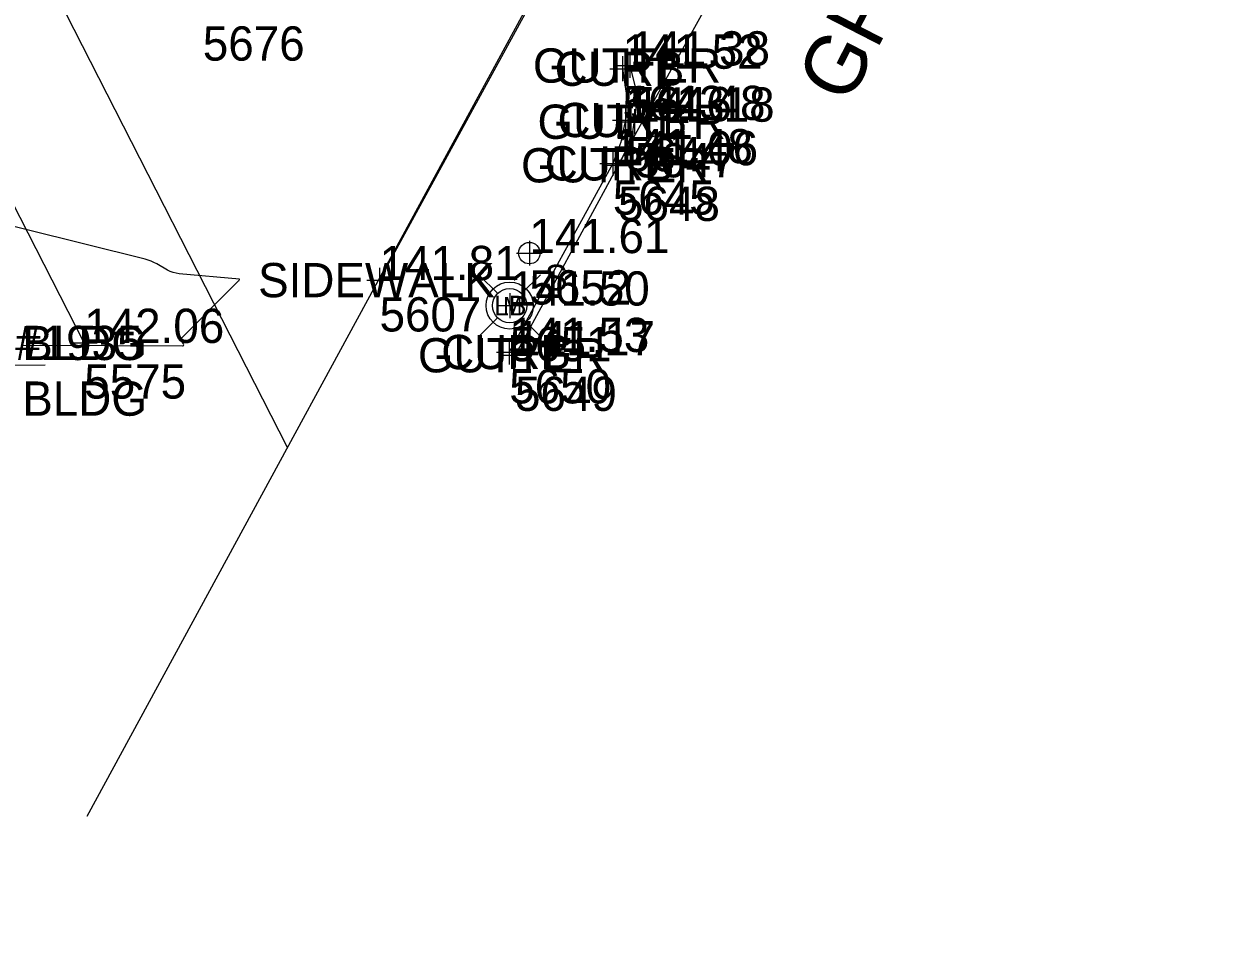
# Model space of a CAD drawing. Extents: x 13482495 to 13483389, y 311646 to 312209.
# Drawn here: x 13483186.7 to 13483297.5, y 311897.5 to 311982.2 of the extents above; entities that cross this region are included whole.
import ezdxf

# ---------------------------------------------------------------- set-up
doc = ezdxf.new("R2010")
doc.units = 0
for name, color, linetype in [('Level 14', 7, 'Continuous'), ('V-ANNO-TEXT', 7, 'Continuous'), ('V-BLDG-OTLN', 7, 'Continuous'), ('V-PROP-LINE', 7, 'Continuous'), ('V-PROP-RWAY', 7, 'Continuous'), ('V-PVMT-BACK', 7, 'Continuous'), ('V-PVMT-ROAD', 7, 'Continuous'), ('V-PVMT-SPOT', 7, 'Continuous'), ('V-SITE-FEAT', 7, 'Continuous'), ('V-SITE-SPOT', 7, 'Continuous'), ('V-SITE-WALK', 7, 'Continuous'), ('V-SURV-PNTS', 7, 'Continuous'), ('V-TOPO-LINE-IDEN', 7, 'Continuous'), ('V-TOPO-MINR', 7, 'Continuous'), ('V-UTIL-OVHD', 7, 'Continuous'), ('V-UTIL-SPOT', 7, 'Continuous')]:
    doc.layers.add(name, color=color, linetype=linetype)

msp = doc.modelspace()

# ---------------------------------------------------------------- linework, layer by layer
at = {"layer": 'Level 14'}
msp.add_circle((13483232.15, 311955.82), 2.2, dxfattribs=at)
at = {"layer": 'V-BLDG-OTLN'}
msp.add_lwpolyline([(13483192.39, 311952.33), (13483171.44, 311993.3), (13483148.19, 311981.61), (13483141.82, 311994.09), (13483137, 311991.7), (13483125.72, 311985.93), (13483092.64, 311968.99), (13483092, 311968.67), (13483074.09, 311959.49), (13483064.66, 311954.6), (13483063.9, 311954.26), (13483051.45, 311947.77), (13483050.51, 311947.31), (13483037.41, 311940.79), (13483029.61, 311936.57), (13483002.49, 311922.78), (13482992.73, 311917.83), (13482979.02, 311910.86), (13482976.31, 311909.36), (13482986.43, 311889.53)], dxfattribs=at)
at = {"layer": 'V-PROP-LINE'}
msp.add_line((13483211.39, 311942.55), (13483176.4, 312011.1), dxfattribs=at)
at = {"layer": 'V-PROP-RWAY'}
msp.add_line((13483192.66, 311908.1), (13483276.39, 312062.11), dxfattribs=at)
at = {"layer": 'V-PVMT-BACK'}
msp.add_lwpolyline([(13483242.7, 311977.95), (13483243.05, 311975.66), (13483243, 311973.36), (13483242.55, 311971.1), (13483241.79, 311969.11), (13483232.11, 311951.48)], dxfattribs=at)
at = {"layer": 'V-PVMT-ROAD'}
for points in [[(13483264.81, 312066.09), (13483266.5, 312067.78), (13483268.45, 312069.17), (13483270.59, 312070.21), (13483272.89, 312070.89), (13483275.26, 312071.17), (13483277.65, 312071.05), (13483279.98, 312070.53), (13483279.99, 312070.53), (13483281.99, 312069.17), (13483283.78, 312067.62), (13483285.28, 312065.79), (13483286.46, 312063.73), (13483287.22, 312061.7), (13483287.93, 312059.34), (13483288.26, 312057.11), (13483288.19, 312054.85), (13483287.73, 312052.64), (13483287.38, 312051.65), (13483273.55, 312025.96), (13483262.05, 312005.41), (13483253.54, 311989.25), (13483242.28, 311968.93), (13483232.65, 311951.18)], [(13483243.39, 311978.25), (13483243.87, 311976.22), (13483243.95, 311974.13), (13483243.63, 311972.07), (13483242.92, 311970.11), (13483242.28, 311968.93)]]:
    msp.add_lwpolyline(points, dxfattribs=at)
at = {"layer": 'V-PVMT-SPOT'}
for p, q in [((13483242.7, 311979.11), (13483242.7, 311976.79)), ((13483243.39, 311979.41), (13483243.39, 311977.09)), ((13483242.19, 311978.25), (13483244.59, 311978.25)), ((13483241.5, 311977.95), (13483243.9, 311977.95)), ((13483242.97, 311974.32), (13483242.97, 311972)), ((13483243.82, 311974.16), (13483243.82, 311971.84)), ((13483241.77, 311973.16), (13483244.17, 311973.16)), ((13483242.62, 311973), (13483245.02, 311973)), ((13483241.79, 311970.27), (13483241.79, 311967.95)), ((13483240.59, 311969.11), (13483242.99, 311969.11)), ((13483242.28, 311970.09), (13483242.28, 311967.77)), ((13483242.28, 311970.09), (13483242.28, 311967.77)), ((13483241.08, 311968.93), (13483243.48, 311968.93)), ((13483241.08, 311968.93), (13483243.48, 311968.93)), ((13483219.99, 311959.36), (13483219.99, 311957.04)), ((13483218.79, 311958.2), (13483221.19, 311958.2)), ((13483232.11, 311952.64), (13483232.11, 311950.32)), ((13483230.91, 311951.48), (13483233.31, 311951.48)), ((13483232.65, 311952.34), (13483232.65, 311950.02)), ((13483231.45, 311951.18), (13483233.85, 311951.18))]:
    msp.add_line(p, q, dxfattribs=at)
at = {"layer": 'V-SITE-FEAT'}
msp.add_circle((13483233.99, 311960.72), 1, dxfattribs=at)
at = {"layer": 'V-SITE-SPOT'}
for p, q in [((13483233.99, 311961.88), (13483233.99, 311959.56)), ((13483232.79, 311960.72), (13483235.19, 311960.72)), ((13483192.39, 311953.49), (13483192.39, 311951.17)), ((13483191.19, 311952.33), (13483193.59, 311952.33))]:
    msp.add_line(p, q, dxfattribs=at)
at = {"layer": 'V-SITE-WALK'}
msp.add_lwpolyline([(13483219.99, 311958.2), (13483240.13, 311995.06), (13483265.09, 312041.64), (13483269.47, 312052.42), (13483267.26, 312057.85), (13483264.69, 312064.33), (13483265.37, 312065.47)], dxfattribs=at)
at = {"layer": 'V-TOPO-MINR'}
for points in [[(13483186.65, 311952.1), (13483187.74, 311952.13), (13483201.56, 311952.05), (13483201.63, 311952.06), (13483201.68, 311952.09), (13483201.69, 311952.14), (13483201.66, 311952.21), (13483201.49, 311952.55), (13483201.47, 311952.63), (13483201.46, 311952.71), (13483201.49, 311952.78), (13483201.54, 311952.85), (13483206.85, 311958.16), (13483206.86, 311958.17), (13483206.87, 311958.18), (13483206.88, 311958.2), (13483206.88, 311958.21), (13483206.91, 311958.27), (13483206.91, 311958.28), (13483206.91, 311958.29), (13483206.9, 311958.3), (13483206.89, 311958.3), (13483201.26, 311958.8), (13483200.97, 311958.84), (13483200.7, 311958.91), (13483200.43, 311959.01), (13483200.17, 311959.14), (13483199.17, 311959.72), (13483198.91, 311959.86), (13483198.65, 311959.97), (13483198.38, 311960.07), (13483198.1, 311960.15), (13483186.81, 311962.96), (13483184.83, 311963.45)], [(13483188.74, 311950.24), (13483179.28, 311950.16)]]:
    msp.add_lwpolyline(points, dxfattribs=at)
at = {"layer": 'V-UTIL-OVHD'}
for p, q in [((13483231.03, 311956.94), (13483229.27, 311958.7)), ((13483233.27, 311956.94), (13483235.03, 311958.7)), ((13483229.23, 311952.9), (13483231.03, 311954.7)), ((13483234.95, 311953.02), (13483233.27, 311954.7))]:
    msp.add_line(p, q, dxfattribs=at)
msp.add_circle((13483232.15, 311955.82), 1.6, dxfattribs=at)
at = {"layer": 'V-UTIL-SPOT'}
for p, q in [((13483232.15, 311956.98), (13483232.15, 311954.66)), ((13483232.15, 311956.98), (13483232.15, 311954.66)), ((13483230.95, 311955.82), (13483233.35, 311955.82)), ((13483230.95, 311955.82), (13483233.35, 311955.82))]:
    msp.add_line(p, q, dxfattribs=at)

# ---------------------------------------------------------------- texts
at = {"layer": 'V-ANNO-TEXT'}
msp.add_text('GRATIOT AVE. (M-3)', height=5.6, rotation=62.8066, dxfattribs=at).set_placement((13483263.78, 311974.45))
at = {"layer": 'V-PVMT-SPOT'}
for s, p in [('141.38', (13483243.39, 311978.25)), ('141.52', (13483242.7, 311977.95)), ('141.48', (13483242.97, 311973.16)), ('141.18', (13483243.82, 311973)), ('141.48', (13483241.79, 311969.11)), ('141.06', (13483242.28, 311968.93)), ('141.06', (13483242.28, 311968.93)), ('141.81', (13483219.99, 311958.2)), ('141.53', (13483232.11, 311951.48)), ('141.17', (13483232.65, 311951.18))]:
    msp.add_text(s, height=3.2, dxfattribs=at).set_placement(p)
at = {"layer": 'V-SITE-FEAT'}
msp.add_text('S', height=2.4, rotation=360, dxfattribs=at).set_placement((13483235.43, 311957.24))
at = {"layer": 'V-SITE-SPOT'}
for s, p in [('141.61', (13483233.99, 311960.72)), ('142.06', (13483192.39, 311952.33))]:
    msp.add_text(s, height=3.2, dxfattribs=at).set_placement(p)
at = {"layer": 'V-SURV-PNTS'}
for s, p in [('5676', (13483203.47, 311978.71)), ('5643', (13483242.7, 311973.15)), ('5646', (13483243.39, 311973.05)), ('5644', (13483242.97, 311968.36)), ('5647', (13483243.82, 311967.8)), ('5645', (13483241.79, 311964.31)), ('5648', (13483242.28, 311963.73)), ('5648', (13483242.28, 311963.73)), ('5652', (13483233.99, 311955.92)), ('5607', (13483219.99, 311953.4)), ('5651', (13483232.15, 311950.62)), ('5651', (13483232.15, 311950.62)), ('5575', (13483192.39, 311947.13)), ('5650', (13483232.11, 311946.68)), ('5649', (13483232.65, 311945.98))]:
    msp.add_text(s, height=3.2, dxfattribs=at).set_placement(p)
at = {"layer": 'V-TOPO-LINE-IDEN'}
for s, p in [('GUTTER', (13483234.32, 311976.65)), (' CURB', (13483235.16, 311976.35)), ('GUTTER', (13483234.75, 311971.4)), (' CURB', (13483235.43, 311971.56)), ('GUTTER', (13483233.21, 311967.33)), ('GUTTER', (13483233.21, 311967.33)), (' CURB', (13483234.24, 311967.51)), ('SIDEWALK', (13483208.64, 311956.6)), ('#1935', (13483185.94, 311950.73)), ('BLDG', (13483186.6, 311950.73)), ('GUTTER', (13483223.58, 311949.58)), (' CURB', (13483224.56, 311949.88)), ('BLDG', (13483186.6, 311945.53))]:
    msp.add_text(s, height=3.2, dxfattribs=at).set_placement(p)
at = {"layer": 'V-UTIL-OVHD'}
for s, height, p in [('LB', 1.843, (13483230.7, 311954.9)), ('M', 1.6, (13483231.55, 311955.02))]:
    msp.add_text(s, height=height, rotation=360, dxfattribs=at).set_placement(p)
at = {"layer": 'V-UTIL-SPOT'}
msp.add_text('141.50', height=3.2, dxfattribs=at).set_placement((13483232.15, 311955.82))
msp.add_text('141.50', height=3.2, dxfattribs=at).set_placement((13483232.15, 311955.82))

doc.saveas('drawing.dxf')
